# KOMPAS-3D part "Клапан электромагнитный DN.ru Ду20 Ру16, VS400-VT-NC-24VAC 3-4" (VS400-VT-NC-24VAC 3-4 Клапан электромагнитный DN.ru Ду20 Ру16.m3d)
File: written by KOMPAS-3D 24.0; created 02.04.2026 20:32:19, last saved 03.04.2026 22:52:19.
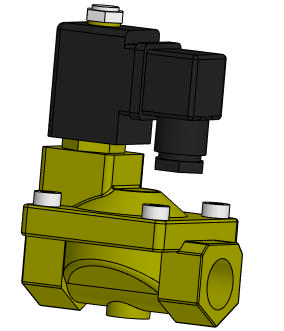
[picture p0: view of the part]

Document properties: Автор: artio; Полное имя файла: C:\Users\artio\OneDrive\Рабочий стол\Клапан электромагнитный DN.ru\VS400-VT-NC\VS400-VT-NC-24VAC 3-4 Клапан электромагнитный DN.ru Ду20 Ру16.m3d

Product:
- Body: Тело 1  | qty 1
    Масса: 1.210539
- Part/product: Клапан электромагнитный DN.ru Ду20 Ру16  | designation VS400-VT-NC-24VAC 3-4
    Масса: 0.954
    Раздел спецификации: Прочие изделия
    Примечание: D130-05498
    additional columns: ef56311e-7521-43dc-8291-0e6108b3d81d; VS400-ET-NC-220VAC 3-4; artio; c; Шероховатость не задана; Да

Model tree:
1. Операция без истории:1

Expressions: VS400-VT-NC-24VAC 3-4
